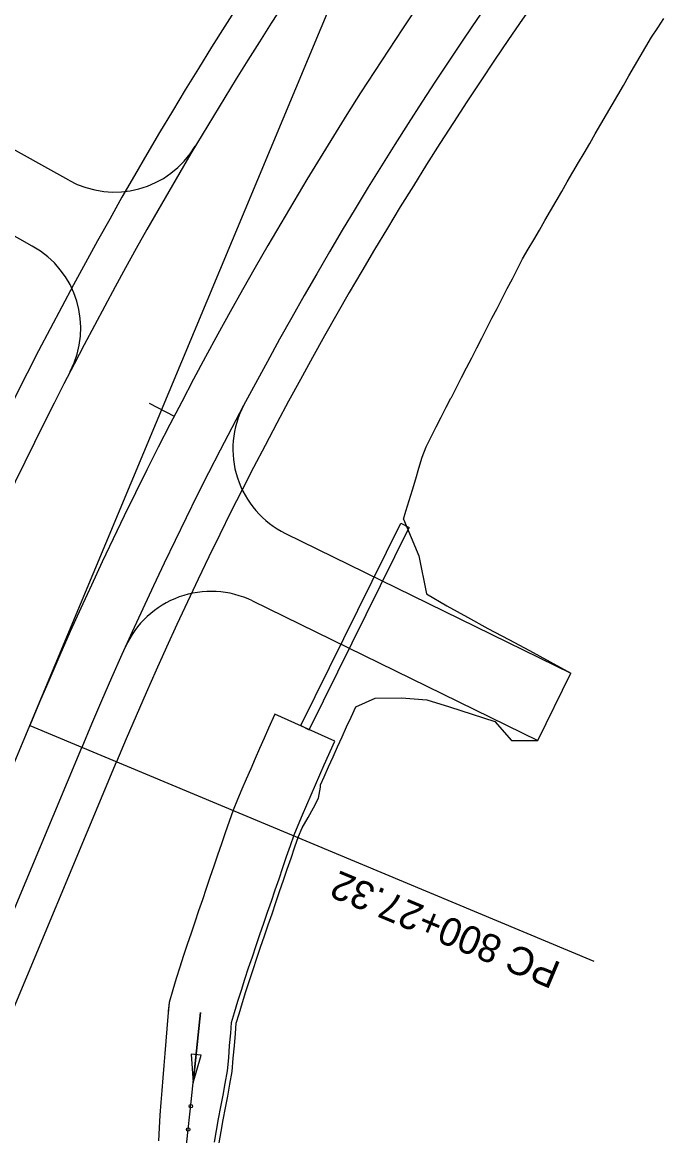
# Model space of a CAD drawing. Extents: x 1237212 to 1293764, y 379349 to 410301.
# Drawn here: x 1283529.3 to 1283666.5, y 404136.8 to 404373.6 of the extents above; entities that cross this region are included whole.
import ezdxf

# ---------------------------------------------------------------- set-up
doc = ezdxf.new("R2010")
doc.units = 0
for name, color, linetype in [('B-Sub-Footing', 7, 'Continuous'), ('B-Sub-Pier Cap', 7, 'Continuous'), ('B-Tbl-Title Block', 7, 'Continuous'), ('B-Title Block (No Plot)', 7, 'Continuous'), ('R_Axis Annot', 7, 'Continuous'), ('R_Exist Surface', 7, 'Continuous'), ('R_Grid', 7, 'Continuous'), ('R_Grid Annot', 7, 'Continuous'), ('R_Horz Alg Annot', 7, 'Continuous'), ('R_Shld', 7, 'Continuous')]:
    doc.layers.add(name, color=color, linetype=linetype)

msp = doc.modelspace()

# ---------------------------------------------------------------- linework, layer by layer
at = {"layer": 'B-Sub-Footing'}
for p, q in [((1283539.17, 404340.02), (1283452.1, 404388.31)), ((1283531.41, 404326.02), (1283452.91, 404369.57)), ((1283585.26, 404264.9), (1283645.91, 404235.2)), ((1283578.22, 404250.53), (1283638.88, 404220.83)), ((1283638.88, 404220.83), (1283645.91, 404235.2))]:
    msp.add_line(p, q, dxfattribs=at)
for centre, start, end in [((1283548.87, 404357.51), 240.9844, 329.2507), ((1283521.71, 404308.53), 332.7181, 60.9844), ((1283594.05, 404282.86), 152.0205, 243.9094), ((1283569.43, 404232.57), 63.9094, 155.7983)]:
    msp.add_arc(centre, 20, start, end, dxfattribs=at)
at = {"layer": 'B-Sub-Pier Cap'}
msp.add_line((1283595.74, 404220.71), (1283582.98, 404226.45), dxfattribs=at)
for points in [[(1283582.98, 404226.45), (1283581.66, 404223.51), (1283580.69, 404221.35), (1283579.74, 404219.18), (1283578.78, 404217.01), (1283577.84, 404214.84), (1283576.91, 404212.66), (1283575.98, 404210.48), (1283575.06, 404208.3), (1283574.11, 404206.03), (1283573.26, 404203.59), (1283572.44, 404201.21), (1283571.62, 404198.84), (1283570.81, 404196.47), (1283570, 404194.1), (1283569.18, 404191.73), (1283568.37, 404189.36), (1283567.56, 404186.98), (1283566.76, 404184.61), (1283565.95, 404182.23), (1283565.15, 404179.86), (1283564.34, 404177.48), (1283563.54, 404175.09), (1283562.75, 404172.65), (1283562.02, 404170.22), (1283561.29, 404167.81), (1283560.48, 404165.1), (1283560.32, 404163.29)], [(1283570.16, 404135.44), (1283570.57, 404137.89), (1283571.03, 404140.38), (1283571.5, 404142.9), (1283571.96, 404145.41), (1283572.43, 404147.92), (1283572.93, 404150.58), (1283573.16, 404153.36), (1283573.37, 404155.97), (1283573.59, 404158.59), (1283573.79, 404160.89), (1283574.42, 404163), (1283575.14, 404165.4), (1283575.86, 404167.78), (1283576.62, 404170.12), (1283577.41, 404172.48), (1283578.21, 404174.85), (1283579.02, 404177.22), (1283579.82, 404179.6), (1283580.63, 404181.97), (1283581.43, 404184.34), (1283582.24, 404186.7), (1283583.05, 404189.07), (1283583.87, 404191.44), (1283584.68, 404193.81), (1283585.49, 404196.18), (1283586.31, 404198.54), (1283587.1, 404200.8), (1283587.96, 404202.87), (1283588.87, 404205.01), (1283589.78, 404207.15), (1283590.7, 404209.29), (1283591.62, 404211.42), (1283592.55, 404213.55), (1283593.5, 404215.68), (1283595.74, 404220.71)], [(1283563.04, 404173.56), (1283562.75, 404172.65), (1283562.02, 404170.22), (1283561.29, 404167.81), (1283560.48, 404165.1), (1283560.23, 404162.17), (1283560.01, 404159.55), (1283559.8, 404156.93), (1283559.58, 404154.31), (1283559.37, 404151.69), (1283559.15, 404149.07), (1283558.94, 404146.44), (1283558.73, 404143.82), (1283558.52, 404141.17), (1283558.35, 404138.46), (1283558.27, 404135.73)]]:
    msp.add_lwpolyline(points, dxfattribs=at)
at = {"layer": 'B-Tbl-Title Block'}
msp.add_line((1283367.9, 403802.7), (1283541.92, 404219.39), dxfattribs=at)
for radius, start in [(869.47, 134.75), (905.47, 138.45801)]:
    msp.add_arc((1284344.24, 403884.33), radius, start, 157.33333, dxfattribs=at)
at = {"layer": 'B-Title Block (No Plot)'}
msp.add_line((1283356.82, 403807.32), (1283530.85, 404224.02), dxfattribs=at)
msp.add_line((1283356.82, 403807.32), (1283530.85, 404224.02), dxfattribs=at)
msp.add_arc((1284344.24, 403884.33), 881.47, 134.75, 157.33333, dxfattribs=at)
msp.add_arc((1284344.24, 403884.33), 881.47, 134.75, 157.33333, dxfattribs=at)
at = {"layer": 'R_Axis Annot'}
for p, q in [((1283588.48, 404224.02), (1283609.74, 404267.05)), ((1283590.27, 404223.13), (1283611.53, 404266.17)), ((1283609.74, 404267.05), (1283611.53, 404266.17)), ((1283588.48, 404224.02), (1283590.27, 404223.13))]:
    msp.add_line(p, q, dxfattribs=at)
at = {"layer": 'R_Exist Surface'}
for points in [[(1283610.36, 404267.92), (1283610.86, 404269.61), (1283611.55, 404271.9), (1283612.24, 404274.2), (1283612.93, 404276.5), (1283613.62, 404278.8), (1283614.31, 404281.11), (1283615.12, 404283.35), (1283616.2, 404285.45), (1283617.28, 404287.55), (1283618.36, 404289.64), (1283619.43, 404291.74), (1283620.43, 404293.69), (1283620.51, 404293.84), (1283621.59, 404295.94), (1283622.67, 404298.04), (1283623.75, 404300.14), (1283624.83, 404302.24), (1283625.91, 404304.35), (1283626.99, 404306.45), (1283628.07, 404308.55), (1283629.15, 404310.66), (1283630.23, 404312.76), (1283631.31, 404314.87), (1283632.39, 404316.97), (1283633.48, 404319.08), (1283634.56, 404321.19), (1283635.67, 404323.28), (1283636.85, 404325.33), (1283638.04, 404327.38), (1283639.23, 404329.42), (1283640.42, 404331.47), (1283641.6, 404333.52), (1283642.79, 404335.56), (1283643.98, 404337.61), (1283645.17, 404339.66), (1283646.36, 404341.71), (1283647.55, 404343.76), (1283648.74, 404345.81), (1283649.93, 404347.86), (1283651.12, 404349.92), (1283652.31, 404351.97), (1283653.5, 404354.02), (1283654.69, 404356.08), (1283655.89, 404358.14), (1283657.08, 404360.19), (1283658.27, 404362.25), (1283659.47, 404364.31), (1283660.66, 404366.37), (1283661.86, 404368.43), (1283663.1, 404370.46), (1283664.39, 404372.45), (1283665.68, 404374.45)], [(1283610.36, 404267.92), (1283613.58, 404260.12), (1283615.2, 404252.07), (1283619.53, 404249.53), (1283623.91, 404247.11), (1283628.3, 404244.7), (1283632.72, 404242.37), (1283637.12, 404239.98), (1283641.51, 404237.56)], [(1283641.51, 404237.56), (1283641.62, 404237.53)], [(1283641.51, 404237.56), (1283645.91, 404235.2)], [(1283600.23, 404228.03), (1283604.34, 404229.89), (1283609.91, 404229.9), (1283615.28, 404229.49), (1283620.12, 404228.01), (1283624.93, 404226.46), (1283629.74, 404224.91)], [(1283592.72, 404211.43), (1283593.47, 404213.15), (1283594.41, 404215.27), (1283595.36, 404217.39), (1283596.31, 404219.51), (1283597.27, 404221.62), (1283598.24, 404223.73), (1283599.22, 404225.85), (1283600.23, 404228.03)], [(1283629.74, 404224.91), (1283633.31, 404220.82), (1283638.88, 404220.83), (1283633.43, 404220.79)], [(1283588.81, 404202.3), (1283590.05, 404204.51), (1283591.21, 404206.54), (1283592.25, 404208.62), (1283592.7, 404210.96), (1283592.72, 404211.43)], [(1283571.15, 404135.29), (1283571.56, 404137.72), (1283572.01, 404140.2), (1283572.48, 404142.71), (1283572.95, 404145.23), (1283573.41, 404147.74), (1283573.92, 404150.45), (1283574.15, 404153.27), (1283574.37, 404155.89), (1283574.59, 404158.51), (1283574.77, 404160.71), (1283575.38, 404162.71), (1283576.1, 404165.12), (1283576.82, 404167.48), (1283577.57, 404169.81), (1283578.36, 404172.16), (1283579.16, 404174.53), (1283579.96, 404176.9), (1283580.77, 404179.27), (1283581.57, 404181.64), (1283582.38, 404184.01), (1283583.19, 404186.38), (1283584, 404188.75), (1283584.81, 404191.12), (1283585.62, 404193.48), (1283586.44, 404195.85), (1283587.25, 404198.21), (1283588.03, 404200.44), (1283588.81, 404202.3)]]:
    msp.add_lwpolyline(points, dxfattribs=at)
at = {"layer": 'R_Grid'}
msp.add_line((1283530.85, 404224.02), (1283598.67, 404386.43), dxfattribs=at)
msp.add_lwpolyline([(1283530.85, 404224.02), (1283650.81, 404173.92)], dxfattribs=at)
msp.add_lwpolyline([(1283530.85, 404224.02), (1283650.81, 404173.92)], dxfattribs=at)
at = {"layer": 'R_Grid Annot'}
msp.add_lwpolyline([(1283556.26, 404292.61), (1283561.59, 404289.85)], dxfattribs=at)
msp.add_lwpolyline([(1283556.26, 404292.61), (1283561.59, 404289.85)], dxfattribs=at)
at = {"layer": 'R_Horz Alg Annot'}
for p, q in [((1283567.28, 404153.92), (1283565.18, 404154.14)), ((1283565.18, 404154.14), (1283565.59, 404148.06)), ((1283567.28, 404153.92), (1283565.18, 404154.14)), ((1283565.18, 404154.14), (1283565.59, 404148.06)), ((1283565.59, 404148.06), (1283567.28, 404153.92)), ((1283565.59, 404148.06), (1283567.28, 404153.92))]:
    msp.add_line(p, q, dxfattribs=at)
for points in [[(1283559.28, 404077.42), (1283560.17, 404084.09), (1283561.08, 404092.56), (1283561.79, 404101.12), (1283562.38, 404109.73), (1283562.92, 404118.36), (1283563.58, 404126.94), (1283564.25, 404135.52), (1283565.16, 404143.99), (1283567.18, 404162.98)], [(1283567.18, 404162.98), (1283565.59, 404148.06)], [(1283567.18, 404162.98), (1283565.59, 404148.06)]]:
    msp.add_lwpolyline(points, dxfattribs=at)
for centre in [(1283565.1, 404143.08), (1283565.1, 404143.08), (1283564.56, 404138.1), (1283564.56, 404138.1)]:
    msp.add_circle(centre, 0.375, dxfattribs=at)
at = {"layer": 'R_Shld'}
msp.add_line((1283448.45, 403974.81), (1283549.3, 404216.31), dxfattribs=at)
for radius, start, end in [(913.47, 136.3373, 157.67823), (861.47, 134.75, 157.33333)]:
    msp.add_arc((1284344.24, 403884.33), radius, start, end, dxfattribs=at)

# ---------------------------------------------------------------- texts
at = {"layer": 'R_Grid'}
msp.add_text('PC 800+27.32', height=6, rotation=157.3333, dxfattribs=at).set_placement((1283644.11, 404173.46))
msp.add_text('PC 800+27.32', height=6, rotation=157.3333, dxfattribs=at).set_placement((1283644.11, 404173.46))

doc.saveas('drawing.dxf')
